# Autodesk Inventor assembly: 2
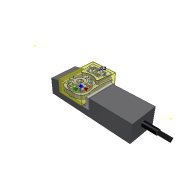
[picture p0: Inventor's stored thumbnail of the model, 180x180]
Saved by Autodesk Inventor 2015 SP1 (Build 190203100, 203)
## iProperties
Created: 2015-06
Part Number: 2
Document SubType Name: Assembly
Designer: suporte
Author: suporte
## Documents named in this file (3)
- C:\Users\suporte\Desktop\#07- CNC Milling\#07- CNC Milling_M2\#07- CNC Milling_M2.iam
- C:\Users\suporte\Desktop\#07- CNC Milling\#07- CNC Milling_M2\#07- CNC Milling_M2.ipt
- C:\Users\suporte\Desktop\#07- CNC Milling\#07- CNC Milling_M2\Small Clamp.ipt
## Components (2 placed, 2 different names)
1. #07- CNC Milling_M2:1 — Flush:1, Flush:2, Flush:3
2. Small Clamp:1 — Flush:1, Flush:2, Flush:3
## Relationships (3: Flush 3)
- Flush:1: #07- CNC Milling_M2:1 ↔ Small Clamp:1
- Flush:2: #07- CNC Milling_M2:1 ↔ Small Clamp:1
- Flush:3: #07- CNC Milling_M2:1 ↔ Small Clamp:1
